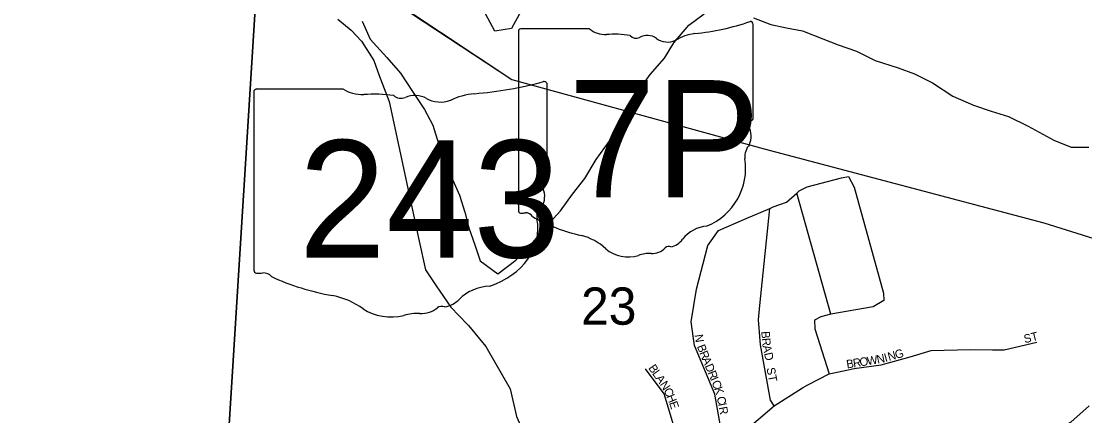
# Model space of a CAD drawing. Extents: x 0 to 34, y 0 to 22.
# Drawn here: x 6.583 to 7.778, y 17.345 to 17.789 of the extents above; entities that cross this region are included whole.
import ezdxf

# ---------------------------------------------------------------- set-up
doc = ezdxf.new("R2010")
doc.units = 0
for name, color, linetype in [('GM_P_State_Alignment', 7, 'Continuous'), ('GM_P_State_Location', 7, 'Continuous'), ('GM_P_State_Shield', 7, 'Continuous'), ('GM_X_Minor_River', 7, 'Continuous'), ('GM_X_Section', 7, 'Continuous'), ('GM_X_Section_Text', 7, 'Continuous'), ('GM_X_State_Location', 7, 'Continuous'), ('GM_X_State_Route', 7, 'Continuous'), ('GM_X_State_Shield', 7, 'Continuous'), ('GM_X_Township_Subdivision', 7, 'Continuous'), ('GM_X_Township_Subdivision_Text', 7, 'Continuous'), ('SH_Data', 7, 'Continuous')]:
    doc.layers.add(name, color=color, linetype=linetype)

msp = doc.modelspace()

# ---------------------------------------------------------------- linework, layer by layer
at = {"layer": 'GM_P_State_Alignment'}
msp.add_lwpolyline([(5.7539, 17.3702), (5.755, 17.3719), (5.7846, 17.4188), (6.0315, 17.5972), (6.2517, 17.7771), (6.3812, 17.906), (6.3923, 17.9142), (6.5211, 17.9881), (6.5265, 17.9911), (6.5405, 17.99), (6.6417, 17.9816), (6.6804, 17.9677), (6.7928, 17.9227), (6.8111, 17.9139), (6.95, 17.8445), (6.9564, 17.8413), (6.9734, 17.8302), (7.1338, 17.7232), (7.4175, 17.6454), (7.7316, 17.5623), (7.9253, 17.5014), (8.1533, 17.4614), (8.4655, 17.4165), (8.5004, 17.4073)], dxfattribs=at)
at = {"layer": 'GM_P_State_Shield'}
for p, q in [((7.4049, 17.6804), (7.4049, 17.7851)), ((7.1413, 17.7767), (7.1413, 17.5766)), ((7.2211, 17.7801), (7.1439, 17.7801)), ((7.4049, 17.6804), (7.4049, 17.6804))]:
    msp.add_line(p, q, dxfattribs=at)
for centre, radius, start, end in [((7.311, 18.053), 0.2796, 275.8445, 288.9065), ((7.402, 17.7855), 0.00294, 351.8621, 97.738), ((7.1443, 17.7771), 0.00305, 98.1301, 188.1301), ((7.2395, 17.8034), 0.0296, 231.6195, 271.1119), ((7.2493, 17.6678), 0.1064, 80.4867, 94.9883), ((7.2735, 17.7782), 0.00855, 219.7921, 297.1024), ((7.286, 17.755), 0.0178, 54.4667, 119.1411), ((7.3467, 17.719), 0.0563, 97.3462, 120.7689), ((7.3089, 17.7868), 0.0214, 233.8562, 294.8282), ((7.4043, 17.6727), 0.00454, 107.944, 210.337), ((7.4018, 17.68), 0.00314, 289.6038, 7.7341), ((7.3754, 17.6595), 0.0273, 340.033, 23.6496), ((7.4155, 17.6366), 0.0198, 136.8065, 186.9296), ((7.3267, 17.6233), 0.0699, 292.3089, 8.9858), ((7.1443, 17.5761), 0.00308, 171.9584, 258.3066), ((7.1448, 17.5966), 0.0235, 267.339, 280.6039), ((7.1496, 17.565), 0.00848, 29.7484, 93.2717), ((7.2567, 17.7448), 0.2019, 240.4129, 257.1985), ((7.3562, 17.5204), 0.0383, 94.4031, 142.5768), ((7.1965, 17.4867), 0.0632, 47.1842, 75.836), ((7.3076, 17.5572), 0.0226, 282.8732, 323.2771), ((7.2648, 17.564), 0.0401, 230.7004, 286.2918), ((7.2909, 17.549), 0.0214, 268.777, 315.5493), ((7.3102, 17.5297), 0.00601, 65.7517, 132.6484), ((7.288, 17.4948), 0.0329, 85.6951, 111.2099)]:
    msp.add_arc(centre, radius, start, end, dxfattribs=at)
at = {"layer": 'GM_X_Minor_River'}
for points in [[(6.9655, 17.789), (6.9746, 17.7685), (6.9935, 17.748), (7.0086, 17.7305), (7.023, 17.7085), (7.0358, 17.6895), (7.0449, 17.672), (7.0516, 17.6515), (7.0592, 17.6333), (7.066, 17.6136), (7.075, 17.5931), (7.081, 17.5741), (7.0856, 17.5566), (7.0923, 17.5376), (7.0984, 17.5194), (7.118, 17.505), (7.1385, 17.5201), (7.1575, 17.5399), (7.1726, 17.5581), (7.1885, 17.5755), (7.2022, 17.5945), (7.2158, 17.612), (7.2287, 17.6332), (7.2432, 17.6537), (7.2538, 17.6719), (7.2629, 17.6902), (7.275, 17.7091), (7.2894, 17.7289), (7.3054, 17.7471), (7.316, 17.7645), (7.3327, 17.7842), (7.3501, 17.7971)], [(7.1442, 17.8003), (7.1336, 17.7806), (7.1147, 17.7775), (7.1018, 17.8018)], [(7.4054, 17.7926), (7.425, 17.785), (7.4424, 17.7812), (7.4606, 17.7781), (7.4833, 17.769), (7.5007, 17.7621), (7.5211, 17.7553), (7.5423, 17.7447), (7.568, 17.7363), (7.5862, 17.7295), (7.6066, 17.7196), (7.6293, 17.7044), (7.6527, 17.6945), (7.6724, 17.6877), (7.6921, 17.6816), (7.714, 17.6709)], [(7.714, 17.6709), (7.7428, 17.655), (7.7624, 17.6474), (7.7821, 17.6474)], [(7.7825, 17.3565), (7.762, 17.3383), (7.7446, 17.3284), (7.7067, 17.3163)]]:
    msp.add_lwpolyline(points, dxfattribs=at)
at = {"layer": 'GM_X_Section'}
for points in [[(5.784, 17.9889), (6.8533, 17.9287), (6.7904, 16.9223), (5.726, 16.9791)], [(6.8533, 17.9287), (7.9078, 17.8715), (7.8396, 16.8632), (6.7904, 16.9223)]]:
    msp.add_lwpolyline(points, close=True, dxfattribs=at)
at = {"layer": 'GM_X_State_Route'}
for points in [[(6.9385, 17.7911), (6.9533, 17.7786), (6.9651, 17.7662), (6.9786, 17.7448), (6.9848, 17.7277), (6.996, 17.6984), (7.0299, 17.5416), (7.0368, 17.5093), (7.0489, 17.4913), (7.0654, 17.4673), (7.0841, 17.4479)], [(7.0841, 17.4479), (7.0851, 17.4469), (7.1048, 17.4232), (7.1321, 17.3755), (7.139, 17.3446), (7.1574, 17.3029), (7.1726, 17.2742), (7.187, 17.2552), (7.211, 17.2029), (7.2123, 17.1996)]]:
    msp.add_lwpolyline(points, dxfattribs=at)
at = {"layer": 'GM_X_State_Shield'}
for p, q in [((6.9438, 17.7126), (6.8473, 17.7126)), ((7.1736, 17.6129), (7.1736, 17.7176)), ((6.8441, 17.7092), (6.8441, 17.5091)), ((7.1736, 17.6129), (7.1736, 17.6129))]:
    msp.add_line(p, q, dxfattribs=at)
for centre, major_axis, start_param, end_param in [((6.8478, 17.7096), (0.00382, 0), 1.712693, 3.28349), ((6.9668, 17.7359), (0.037, 0), 4.042523, 4.731795), ((7.0562, 17.9855), (0.3495, 0), 4.814394, 5.042369), ((7.17, 17.718), (0.00367, 0), 6.141152, 7.989035), ((6.9791, 17.6003), (0.133, 0), 1.404758, 1.657858), ((7.0093, 17.7107), (0.0107, 0), 3.836095, 5.185415), ((7.025, 17.6875), (0.0222, 0), 0.950623, 2.079405), ((7.0536, 17.7193), (0.0267, 0), 4.081561, 5.145723), ((7.1008, 17.6515), (0.0703, 0), 1.699011, 2.107814), ((7.1728, 17.6052), (0.00568, 0), 1.883978, 3.671073), ((7.1367, 17.592), (0.0341, 0), 5.934695, 6.695948), ((7.1697, 17.6125), (0.00393, 0), 5.05454, 6.418171), ((7.1868, 17.5691), (0.0248, 0), 2.387724, 3.262537), ((7.0758, 17.5558), (0.0874, 0), 5.101752, 6.440018), ((6.8479, 17.5086), (0.00385, 0), 3.00124, 4.508301), ((6.8485, 17.5291), (0.0294, 0), 4.665946, 4.897461), ((6.8545, 17.4975), (0.0106, 0), 0.519207, 1.627899), ((6.9883, 17.6773), (0.2524, 0), 4.195997, 4.488961), ((7.1127, 17.4529), (0.0479, 0), 1.647645, 2.488434), ((6.913, 17.4192), (0.079, 0), 0.823519, 1.323587), ((7.052, 17.4897), (0.0282, 0), 4.937069, 5.64225), ((6.9985, 17.4965), (0.0501, 0), 4.026481, 4.996735), ((7.0274, 17.4273), (0.0412, 0), 1.495662, 1.94098), ((7.0311, 17.4815), (0.0267, 0), 4.691044, 5.507374), ((7.0552, 17.4622), (0.00752, 0), 1.147584, 2.315152)]:
    msp.add_ellipse(centre, major_axis=major_axis, ratio=0.8, start_param=start_param, end_param=end_param, dxfattribs=at)
at = {"layer": 'GM_X_Township_Subdivision'}
for points in [[(7.3753, 17.2936), (7.362, 17.3697), (7.339, 17.4244), (7.3352, 17.451), (7.3413, 17.4878), (7.3541, 17.5368), (7.3659, 17.5535), (7.3973, 17.5672), (7.4237, 17.5784), (7.4277, 17.5801), (7.4424, 17.5855), (7.4542, 17.5957), (7.4568, 17.598), (7.4659, 17.6026), (7.5042, 17.6128), (7.5121, 17.6144), (7.5186, 17.6022), (7.5516, 17.483), (7.552, 17.475), (7.5399, 17.4678), (7.4924, 17.4595), (7.481, 17.4566), (7.4741, 17.4529), (7.4743, 17.443), (7.4905, 17.3926)], [(7.4924, 17.4595), (7.4542, 17.5957)], [(7.4286, 17.3567), (7.4245, 17.3628), (7.4131, 17.4252), (7.4109, 17.4532), (7.4125, 17.4693), (7.4237, 17.5784)], [(7.6745, 17.4195), (7.687, 17.4193), (7.7237, 17.428)], [(7.5066, 17.3958), (7.5187, 17.3983), (7.549, 17.4025), (7.5816, 17.4116), (7.6051, 17.4188), (7.6494, 17.42), (7.6738, 17.4195), (7.6745, 17.4195)], [(7.2158, 17.1902), (7.2293, 17.1883), (7.2538, 17.1914), (7.2786, 17.1956), (7.297, 17.1997), (7.3046, 17.2038), (7.3217, 17.219), (7.3357, 17.233), (7.3477, 17.2422), (7.3649, 17.2645), (7.3788, 17.2771), (7.3833, 17.2945), (7.3925, 17.3257), (7.4286, 17.3567), (7.4604, 17.3766), (7.4666, 17.3801), (7.4905, 17.3926), (7.5066, 17.3958)], [(7.3217, 17.219), (7.3201, 17.2252), (7.3186, 17.2314), (7.3189, 17.2432), (7.3211, 17.2825), (7.3189, 17.3133), (7.3157, 17.3351), (7.3049, 17.37), (7.2841, 17.3981)]]:
    msp.add_lwpolyline(points, dxfattribs=at)
at = {"layer": 'SH_Data'}
msp.add_lwpolyline([(5.7846, 17.4188), (6.0315, 17.5972), (6.2517, 17.7771), (6.3812, 17.906), (6.5265, 17.9911), (6.6417, 17.9816), (6.7928, 17.9227), (6.95, 17.8445), (7.1338, 17.7232), (7.4175, 17.6454), (7.7316, 17.5623), (7.9253, 17.5014)], dxfattribs=at)

# ---------------------------------------------------------------- texts
at = {"layer": 'GM_P_State_Location'}
for s in ['s', 'r']:
    msp.add_text(s, height=0.000189, dxfattribs=at).set_placement((7.2701, 17.6633))
msp.add_text('7P', height=0.000189, rotation=0, dxfattribs=at).set_placement((7.2183, 17.6496))
at = {"layer": 'GM_P_State_Shield'}
msp.add_text('7P', height=0.13184, dxfattribs=at).set_placement((7.1973, 17.5907))
at = {"layer": 'GM_X_Section_Text'}
msp.add_text('23', height=0.04186, rotation=0, dxfattribs=at).set_placement((7.2116, 17.4477))
at = {"layer": 'GM_X_State_Location'}
for s in ['s', 'r']:
    msp.add_text(s, height=0.000189, dxfattribs=at).set_placement((7.0051, 17.5958))
msp.add_text('243', height=0.000189, rotation=0, dxfattribs=at).set_placement((6.9383, 17.5821))
at = {"layer": 'GM_X_State_Shield'}
msp.add_text('243', height=0.13184, dxfattribs=at).set_placement((6.8944, 17.5232))
at = {"layer": 'GM_X_Township_Subdivision_Text'}
for s, rotation, p in [('N', 278.843, (7.3392, 17.4362)), ('B', 273.3533, (7.4142, 17.4402)), ('ST', 14.0362, (7.7104, 17.4268)), ('B', 290.6737, (7.3417, 17.4234)), ('R', 275.1314, (7.4147, 17.4324)), ('A', 281.3439, (7.4155, 17.4238)), ('R', 292.521, (7.3444, 17.4161)), ('D', 282.2743, (7.4172, 17.4155)), ('W', 8.6974, (7.5336, 17.4021)), ('N', 12.307, (7.5449, 17.4038)), ('I', 15.5883, (7.5536, 17.4057)), ('N', 15.7018, (7.5577, 17.4069)), ('G', 15.7088, (7.5657, 17.4091)), ('B', 305.22, (7.2868, 17.399)), ('A', 292.4742, (7.3473, 17.4092)), ('D', 292.498, (7.3505, 17.4015)), ('ST', 280.627, (7.42, 17.3988)), ('B', 8.7007, (7.5105, 17.3985)), ('R', 8.7007, (7.5179, 17.3997)), ('O', 8.7005, (7.5253, 17.4008)), ('L', 305.22, (7.2911, 17.3928)), ('A', 305.22, (7.2949, 17.3874)), ('R', 292.4791, (7.3537, 17.3938)), ('I', 292.5186, (7.3566, 17.3868)), ('N', 302.5463, (7.2997, 17.3807)), ('C', 297.1988, (7.304, 17.3738)), ('C', 292.5038, (7.3581, 17.383)), ('K', 288.8505, (7.361, 17.3762)), ('H', 291.8513, (7.3074, 17.3674)), ('C', 280.8968, (7.3641, 17.3662)), ('E', 289.1775, (7.3104, 17.3598)), ('I', 280.6391, (7.3655, 17.3589)), ('R', 280.6003, (7.3663, 17.3548))]:
    msp.add_text(s, height=0.00947, rotation=rotation, dxfattribs=at).set_placement(p)

doc.saveas('drawing.dxf')
